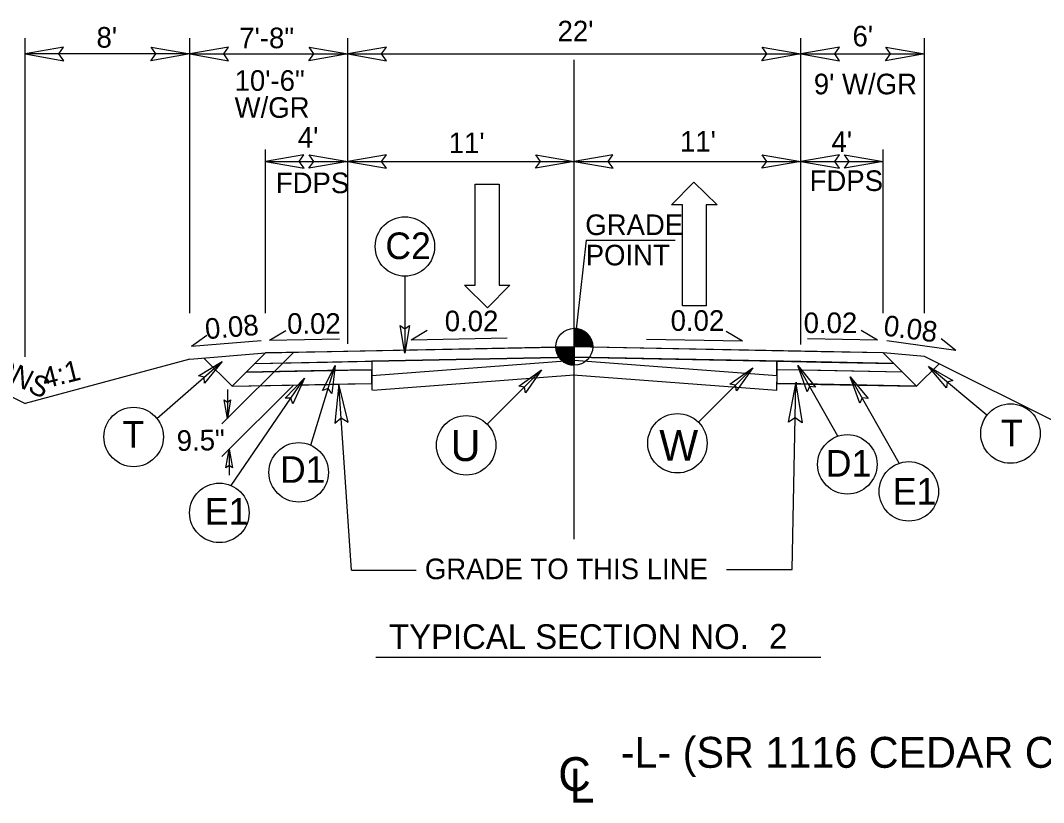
# Model space of a CAD drawing. Extents: x 573732 to 574187, y -53389 to -53257.
# Drawn here: x 573830.28 to 573879.96, y -53323.15 to -53285.19 of the extents above; entities that cross this region are included whole.
import ezdxf

# ---------------------------------------------------------------- set-up
doc = ezdxf.new("R2010")
doc.units = 0
for name, color, linetype in [('Old_Level_11', 7, 'Continuous'), ('Prop Dimension', 7, 'Continuous'), ('Prop Lane Arrow CELL', 7, 'Continuous'), ('Prop Shade Heavy', 7, 'Continuous'), ('Prop Shade Light', 7, 'Continuous'), ('Prop Shade Medium', 7, 'Continuous'), ('Typical Grade Point Symbol CELL', 7, 'Continuous'), ('Typical ID Circle CELL', 7, 'Continuous'), ('Typical Pavement Slope CELL', 7, 'Continuous'), ('Typical Pavement Slope Information CELL', 7, 'Continuous'), ('Typical Shoulder Slope CELL', 7, 'Continuous'), ('Typical Shoulder Slope Information CELL', 7, 'Continuous'), ('Typical Slope Point Local CELL', 7, 'Continuous'), ('Typical Terminator CELL', 7, 'Continuous'), ('Typical Text Centerline CELL', 7, 'Continuous'), ('Typical Text General CELL', 7, 'Continuous'), ('Typical Text Grade Point CELL', 7, 'Continuous'), ('Typical Text ID Circle CELL', 7, 'Continuous'), ('Typical Text Label CELL', 7, 'Continuous')]:
    doc.layers.add(name, color=color, linetype=linetype)

msp = doc.modelspace()

# ---------------------------------------------------------------- linework, layer by layer
at = {"layer": 'Old_Level_11'}
for points in [[(573840.48, -53303.606), (573840.325, -53304.506), (573840.165, -53303.601), (573840.325, -53303.716)], [(573840.255, -53306.905), (573840.41, -53306.005), (573840.57, -53306.91), (573840.41, -53306.795)]]:
    msp.add_lwpolyline(points, close=True, dxfattribs=at)
at = {"layer": 'Prop Dimension'}
for p, q in [((573830.501, -53301.516), (573830.501, -53286.055)), ((573838.501, -53299.402), (573838.501, -53286.055)), ((573846.171, -53300.89), (573846.171, -53286.055)), ((573868.171, -53300.915), (573868.171, -53286.055)), ((573874.171, -53299.402), (573874.171, -53286.055)), ((573838.501, -53286.812), (573830.501, -53286.812)), ((573838.501, -53286.812), (573846.171, -53286.812)), ((573846.171, -53286.812), (573868.171, -53286.812)), ((573868.171, -53286.812), (573874.171, -53286.812)), ((573842.171, -53299.402), (573842.171, -53291.451)), ((573872.171, -53299.402), (573872.171, -53291.451)), ((573842.171, -53292.027), (573846.171, -53292.027)), ((573846.171, -53292.027), (573857.171, -53292.027)), ((573857.171, -53292.027), (573868.171, -53292.027)), ((573868.171, -53292.027), (573872.171, -53292.027)), ((573857.747, -53295.851), (573857.171, -53301.028)), ((573857.747, -53295.851), (573862.067, -53295.851)), ((573843.529, -53301.301), (573840.059, -53304.772)), ((573843.529, -53302.885), (573840.059, -53306.356)), ((573840.325, -53303.109), (573840.325, -53304.506)), ((573846.356, -53311.868), (573845.741, -53302.84)), ((573867.742, -53311.834), (573867.936, -53302.827)), ((573840.41, -53306.005), (573840.41, -53307.259)), ((573846.356, -53311.868), (573849.496, -53311.868)), ((573864.558, -53311.834), (573867.742, -53311.834))]:
    msp.add_line(p, q, dxfattribs=at)
at = {"layer": 'Prop Lane Arrow CELL'}
for p, q in [((573852.364, -53298.034), (573852.364, -53293.134)), ((573852.364, -53293.134), (573853.519, -53293.134)), ((573853.519, -53293.134), (573853.519, -53298.034)), ((573861.898, -53294.14), (573862.983, -53293.037)), ((573862.983, -53293.037), (573864.103, -53294.14)), ((573862.423, -53294.14), (573861.898, -53294.14)), ((573862.423, -53299.04), (573862.423, -53294.14)), ((573864.103, -53294.14), (573863.578, -53294.14)), ((573863.578, -53294.14), (573863.578, -53299.04)), ((573852.959, -53299.137), (573851.839, -53298.034)), ((573851.839, -53298.034), (573852.364, -53298.034)), ((573854.044, -53298.034), (573852.959, -53299.137)), ((573853.519, -53298.034), (573854.044, -53298.034)), ((573863.578, -53299.04), (573862.423, -53299.04))]:
    msp.add_line(p, q, dxfattribs=at)
at = {"layer": 'Prop Shade Heavy'}
for points in [[(573857.171, -53301.528), (573857.161, -53301.528), (573847.332, -53301.725), (573847.332, -53302.141), (573847.332, -53302.424), (573857.171, -53301.681), (573857.171, -53301.528)], [(573857.181, -53301.528), (573857.171, -53301.528), (573857.171, -53301.681), (573867.009, -53302.424), (573867.009, -53302.141), (573867.009, -53301.725), (573857.181, -53301.528)]]:
    msp.add_lwpolyline(points, dxfattribs=at)
at = {"layer": 'Prop Shade Light'}
for p, q in [((573857.171, -53301.028), (573845.175, -53301.268)), ((573869.166, -53301.268), (573857.171, -53301.028)), ((573842.171, -53301.329), (573841.66, -53301.84)), ((573845.175, -53301.268), (573842.171, -53301.329)), ((573847.332, -53301.725), (573857.161, -53301.528)), ((573857.161, -53301.528), (573857.171, -53301.528)), ((573872.171, -53301.329), (573869.166, -53301.268)), ((573872.681, -53301.84), (573872.171, -53301.329)), ((573841.66, -53301.84), (573845.185, -53301.767)), ((573845.185, -53301.767), (573847.332, -53301.725)), ((573867.009, -53301.725), (573869.156, -53301.767)), ((573869.156, -53301.767), (573872.681, -53301.84))]:
    msp.add_line(p, q, dxfattribs=at)
msp.add_lwpolyline([(573857.171, -53301.528), (573857.181, -53301.528), (573867.009, -53301.725)], dxfattribs=at)
at = {"layer": 'Prop Shade Medium'}
for p, q in [((573841.234, -53302.265), (573840.554, -53302.946)), ((573845.193, -53302.184), (573841.234, -53302.265)), ((573847.332, -53302.141), (573845.193, -53302.184)), ((573847.332, -53302.424), (573847.332, -53302.141)), ((573847.332, -53302.725), (573847.332, -53302.424)), ((573869.148, -53302.184), (573867.009, -53302.141)), ((573873.107, -53302.265), (573869.148, -53302.184)), ((573873.787, -53302.946), (573873.107, -53302.265)), ((573840.554, -53302.946), (573845.207, -53302.851)), ((573847.332, -53302.808), (573847.332, -53302.725)), ((573867.009, -53302.725), (573867.009, -53302.808)), ((573867.009, -53302.808), (573867.922, -53302.826)), ((573867.951, -53302.827), (573869.135, -53302.851)), ((573869.135, -53302.851), (573873.787, -53302.946))]:
    msp.add_line(p, q, dxfattribs=at)
for points in [[(573867.009, -53302.141), (573867.009, -53302.424), (573867.009, -53302.725)], [(573845.207, -53302.851), (573845.741, -53302.84), (573847.332, -53302.808)], [(573867.922, -53302.826), (573867.938, -53302.743), (573867.951, -53302.827)]]:
    msp.add_lwpolyline(points, dxfattribs=at)
at = {"layer": 'Typical Grade Point Symbol CELL'}
for p, q in [((573857.171, -53301.028), (573857.171, -53300.132)), ((573856.275, -53301.028), (573857.171, -53301.028)), ((573857.169, -53301.923), (573857.171, -53301.028)), ((573857.171, -53301.028), (573857.169, -53301.923)), ((573858.066, -53301.028), (573857.171, -53301.028))]:
    msp.add_line(p, q, dxfattribs=at)
for points in [[(573857.179, -53300.132), (573857.179, -53300.132), (573857.179, -53301.028)], [(573857.196, -53300.132), (573857.196, -53301.028)], [(573857.214, -53300.134), (573857.214, -53301.028)], [(573857.232, -53300.134), (573857.232, -53301.028)], [(573857.25, -53300.136), (573857.25, -53301.028)], [(573857.268, -53300.138), (573857.268, -53301.028)], [(573857.286, -53300.14), (573857.286, -53301.028)], [(573857.304, -53300.142), (573857.304, -53301.028)], [(573857.322, -53300.144), (573857.322, -53301.028)], [(573857.34, -53300.148), (573857.34, -53301.028)], [(573857.358, -53300.152), (573857.358, -53301.028)], [(573857.376, -53300.156), (573857.376, -53301.028)], [(573857.393, -53300.16), (573857.393, -53301.028)], [(573857.411, -53300.166), (573857.411, -53301.028)], [(573857.429, -53300.17), (573857.429, -53301.028)], [(573857.447, -53300.176), (573857.447, -53301.028)], [(573857.465, -53300.182), (573857.465, -53301.028)], [(573857.483, -53300.188), (573857.483, -53301.028)], [(573857.501, -53300.196), (573857.501, -53301.028)], [(573857.519, -53300.204), (573857.519, -53301.028)], [(573857.537, -53300.212), (573857.537, -53301.028)], [(573857.555, -53300.22), (573857.555, -53301.028)], [(573857.572, -53300.228), (573857.572, -53301.028)], [(573857.59, -53300.238), (573857.59, -53301.028)], [(573857.608, -53300.248), (573857.608, -53301.028)], [(573857.626, -53300.258), (573857.626, -53301.028)], [(573857.644, -53300.268), (573857.644, -53301.028)], [(573857.662, -53300.28), (573857.662, -53301.028)], [(573857.68, -53300.292), (573857.68, -53301.028)], [(573857.698, -53300.305), (573857.698, -53301.028)], [(573857.716, -53300.317), (573857.716, -53301.028)], [(573857.734, -53300.331), (573857.734, -53301.028)], [(573857.751, -53300.347), (573857.751, -53301.028)], [(573857.769, -53300.363), (573857.769, -53301.028)], [(573857.787, -53300.379), (573857.787, -53301.028)], [(573857.805, -53300.397), (573857.805, -53301.028)], [(573857.823, -53300.415), (573857.823, -53301.028)], [(573857.841, -53300.435), (573857.841, -53301.028)], [(573857.859, -53300.457), (573857.859, -53301.028)], [(573857.877, -53300.479), (573857.877, -53301.028)], [(573857.895, -53300.502), (573857.895, -53301.028)], [(573857.913, -53300.528), (573857.913, -53301.028)], [(573857.931, -53300.556), (573857.931, -53301.028)], [(573857.948, -53300.586), (573857.948, -53301.028)], [(573857.966, -53300.618), (573857.966, -53301.028)], [(573856.279, -53301.028), (573856.279, -53301.125)], [(573856.297, -53301.028), (573856.297, -53301.231)], [(573856.315, -53301.028), (573856.315, -53301.294)], [(573856.333, -53301.028), (573856.333, -53301.348)], [(573856.351, -53301.028), (573856.351, -53301.39)], [(573856.369, -53301.028), (573856.369, -53301.427)], [(573856.387, -53301.028), (573856.387, -53301.461)], [(573856.405, -53301.028), (573856.405, -53301.493)], [(573856.423, -53301.028), (573856.423, -53301.521)], [(573856.441, -53301.028), (573856.441, -53301.547)], [(573856.458, -53301.028), (573856.458, -53301.571)], [(573856.476, -53301.028), (573856.476, -53301.593)], [(573856.494, -53301.028), (573856.494, -53301.614)], [(573856.512, -53301.028), (573856.512, -53301.634)], [(573856.53, -53301.028), (573856.53, -53301.654)], [(573856.548, -53301.028), (573856.548, -53301.672)], [(573856.566, -53301.028), (573856.566, -53301.688)], [(573856.584, -53301.028), (573856.584, -53301.704)], [(573856.602, -53301.028), (573856.602, -53301.72)], [(573856.62, -53301.028), (573856.62, -53301.734)], [(573856.637, -53301.028), (573856.637, -53301.748)], [(573856.655, -53301.028), (573856.655, -53301.76)], [(573856.673, -53301.028), (573856.673, -53301.772)], [(573856.691, -53301.028), (573856.691, -53301.784)], [(573856.709, -53301.028), (573856.709, -53301.795)], [(573856.727, -53301.028), (573856.727, -53301.805)], [(573856.745, -53301.028), (573856.745, -53301.815)], [(573856.763, -53301.028), (573856.763, -53301.825)], [(573856.781, -53301.028), (573856.781, -53301.833)], [(573856.799, -53301.028), (573856.799, -53301.841)], [(573856.817, -53301.028), (573856.817, -53301.849)], [(573856.834, -53301.028), (573856.834, -53301.857)], [(573856.852, -53301.028), (573856.852, -53301.865)], [(573856.87, -53301.028), (573856.87, -53301.871)], [(573856.888, -53301.028), (573856.888, -53301.877)], [(573856.906, -53301.028), (573856.906, -53301.883)], [(573856.924, -53301.028), (573856.924, -53301.887)], [(573856.942, -53301.028), (573856.942, -53301.893)], [(573856.96, -53301.028), (573856.96, -53301.897)], [(573856.978, -53301.028), (573856.978, -53301.901)], [(573856.996, -53301.028), (573856.996, -53301.905)], [(573857.013, -53301.028), (573857.013, -53301.909)], [(573857.031, -53301.028), (573857.031, -53301.911)], [(573857.049, -53301.028), (573857.049, -53301.915)], [(573857.067, -53301.028), (573857.067, -53301.917)], [(573857.085, -53301.028), (573857.085, -53301.919)], [(573857.103, -53301.028), (573857.103, -53301.921)], [(573857.121, -53301.028), (573857.121, -53301.921)], [(573857.139, -53301.028), (573857.139, -53301.923)], [(573857.157, -53301.028), (573857.157, -53301.923), (573857.157, -53301.923)], [(573857.984, -53300.656), (573857.984, -53301.028)], [(573858.002, -53300.697), (573858.002, -53301.028)], [(573858.02, -53300.747), (573858.02, -53301.028)], [(573858.038, -53300.809), (573858.038, -53301.028)], [(573858.056, -53300.9), (573858.056, -53301.028)]]:
    msp.add_lwpolyline(points, dxfattribs=at)
msp.add_circle((573857.17, -53301.027), 0.895, dxfattribs=at)
for start, end in [(359.9905, 89.9905), (179.9905, 269.9905)]:
    msp.add_arc((573857.17, -53301.027), 0.895, start, end, dxfattribs=at)
at = {"layer": 'Typical ID Circle CELL'}
for p, q in [((573848.946, -53297.602), (573848.946, -53301.33)), ((573836.907, -53304.513), (573840.075, -53301.735)), ((573844.382, -53305.808), (573845.561, -53301.935)), ((573863.197, -53304.691), (573865.835, -53302.055)), ((573869.966, -53305.369), (573868.02, -53301.939)), ((573877.21, -53304.353), (573874.369, -53301.987)), ((573840.509, -53307.766), (573844.07, -53302.549)), ((573852.941, -53304.789), (573855.579, -53302.153)), ((573872.95, -53306.681), (573870.569, -53302.483))]:
    msp.add_line(p, q, dxfattribs=at)
for centre in [(573848.946, -53296.16), (573835.773, -53305.404), (573878.349, -53305.24), (573851.922, -53305.809), (573862.178, -53305.711), (573870.43, -53306.735), (573843.789, -53307.123), (573873.415, -53308.047), (573839.936, -53309.091)]:
    msp.add_circle(centre, 1.443, dxfattribs=at)
at = {"layer": 'Typical Pavement Slope CELL'}
for p, q in [((573846.171, -53301.248), (573857.171, -53301.028)), ((573868.171, -53301.248), (573857.171, -53301.028)), ((573846.171, -53301.748), (573857.181, -53301.528)), ((573868.171, -53301.748), (573857.161, -53301.528)), ((573846.171, -53302.165), (573847.332, -53302.141)), ((573868.171, -53302.165), (573867.009, -53302.141)), ((573846.171, -53302.831), (573847.345, -53302.808)), ((573868.171, -53302.831), (573866.996, -53302.808))]:
    msp.add_line(p, q, dxfattribs=at)
at = {"layer": 'Typical Pavement Slope Information CELL'}
for p, q in [((573838.579, -53300.991), (573839.332, -53300.471)), ((573842.377, -53300.712), (573843.16, -53300.239)), ((573849.25, -53300.688), (573850.033, -53300.215)), ((573849.25, -53300.688), (573853.91, -53300.595)), ((573865.336, -53300.763), (573864.553, -53300.29)), ((573871.889, -53300.713), (573871.106, -53300.239)), ((573838.579, -53300.991), (573841.964, -53300.716)), ((573842.377, -53300.712), (573845.772, -53300.644)), ((573865.336, -53300.763), (573860.675, -53300.67)), ((573871.889, -53300.713), (573868.494, -53300.645)), ((573875.701, -53301.207), (573872.339, -53300.731)), ((573875.701, -53301.207), (573874.981, -53300.643))]:
    msp.add_line(p, q, dxfattribs=at)
at = {"layer": 'Typical Shoulder Slope CELL'}
for p, q in [((573838.501, -53301.635), (573842.171, -53301.329)), ((573840.554, -53302.946), (573839.185, -53301.578)), ((573840.554, -53302.946), (573842.171, -53301.329)), ((573842.171, -53301.329), (573846.171, -53301.247)), ((573872.171, -53301.329), (573868.171, -53301.247)), ((573874.171, -53301.496), (573872.171, -53301.329)), ((573873.787, -53302.946), (573872.171, -53301.329)), ((573841.66, -53301.84), (573846.171, -53301.747)), ((573847.332, -53302.424), (573857.171, -53301.681)), ((573847.332, -53301.725), (573847.332, -53302.725)), ((573857.171, -53301.681), (573867.009, -53302.424)), ((573867.009, -53301.725), (573867.009, -53302.725)), ((573872.681, -53301.84), (573868.171, -53301.747)), ((573873.787, -53302.946), (573874.882, -53301.851)), ((573841.234, -53302.265), (573846.171, -53302.164)), ((573847.385, -53303.132), (573857.171, -53302.393)), ((573857.117, -53302.389), (573867.009, -53303.136)), ((573873.107, -53302.265), (573868.171, -53302.164)), ((573840.554, -53302.946), (573846.171, -53302.831)), ((573847.332, -53302.724), (573847.332, -53303.136)), ((573867.009, -53303.136), (573867.009, -53302.725)), ((573873.787, -53302.946), (573868.171, -53302.831))]:
    msp.add_line(p, q, dxfattribs=at)
at = {"layer": 'Typical Slope Point Local CELL'}
for p, q in [((573816.884, -53296.978), (573830.501, -53303.786)), ((573896.67, -53312.746), (573874.171, -53301.496)), ((573838.501, -53301.635), (573830.501, -53303.786))]:
    msp.add_line(p, q, dxfattribs=at)
at = {"layer": 'Typical Terminator CELL'}
for points in [[(573832.375, -53286.489), (573830.501, -53286.812), (573832.386, -53287.145), (573832.146, -53286.812)], [(573836.626, -53286.489), (573838.501, -53286.812), (573836.615, -53287.145), (573836.855, -53286.812)], [(573840.375, -53286.489), (573838.501, -53286.812), (573840.386, -53287.145), (573840.146, -53286.812)], [(573844.296, -53286.489), (573846.171, -53286.812), (573844.285, -53287.145), (573844.525, -53286.812)], [(573848.045, -53286.489), (573846.171, -53286.812), (573848.056, -53287.145), (573847.816, -53286.812)], [(573866.296, -53286.489), (573868.171, -53286.812), (573866.285, -53287.145), (573866.525, -53286.812)], [(573870.045, -53286.489), (573868.171, -53286.812), (573870.056, -53287.145), (573869.816, -53286.812)], [(573872.296, -53286.489), (573874.171, -53286.812), (573872.285, -53287.145), (573872.525, -53286.812)], [(573844.045, -53291.705), (573842.171, -53292.027), (573844.056, -53292.361), (573843.816, -53292.027)], [(573844.296, -53291.705), (573846.171, -53292.027), (573844.285, -53292.361), (573844.525, -53292.027)], [(573848.045, -53291.705), (573846.171, -53292.027), (573848.056, -53292.361), (573847.816, -53292.027)], [(573855.296, -53291.705), (573857.171, -53292.027), (573855.285, -53292.361), (573855.525, -53292.027)], [(573859.045, -53291.705), (573857.171, -53292.027), (573859.056, -53292.361), (573858.816, -53292.027)], [(573866.296, -53291.705), (573868.171, -53292.027), (573866.285, -53292.361), (573866.525, -53292.027)], [(573870.045, -53291.705), (573868.171, -53292.027), (573870.056, -53292.361), (573869.816, -53292.027)], [(573870.296, -53291.705), (573872.171, -53292.027), (573870.285, -53292.361), (573870.525, -53292.027)], [(573849.176, -53299.995), (573848.946, -53301.33), (573848.709, -53299.987), (573848.946, -53300.158)], [(573838.919, -53302.442), (573840.075, -53301.735), (573839.222, -53302.799), (573839.194, -53302.508)], [(573844.952, -53303.146), (573845.561, -53301.935), (573845.397, -53303.289), (573845.22, -53303.057)], [(573864.727, -53302.836), (573865.835, -53302.055), (573865.052, -53303.172), (573865.005, -53302.884)], [(573868.479, -53303.214), (573868.02, -53301.939), (573868.889, -53302.99), (573868.599, -53302.959)], [(573875.248, -53303.019), (573874.369, -53301.987), (573875.553, -53302.664), (573875.27, -53302.738)], [(573843.127, -53303.522), (573844.07, -53302.549), (573843.509, -53303.792), (573843.409, -53303.517)], [(573854.471, -53302.935), (573855.579, -53302.153), (573854.797, -53303.27), (573854.75, -53302.982)], [(573871.028, -53303.759), (573870.569, -53302.483), (573871.438, -53303.534), (573871.148, -53303.503)], [(573846.19, -53304.688), (573845.741, -53302.84), (573845.536, -53304.743), (573845.853, -53304.481)], [(573867.573, -53304.694), (573867.936, -53302.827), (573868.229, -53304.719), (573867.901, -53304.472)]]:
    msp.add_lwpolyline(points, close=True, dxfattribs=at)
at = {"layer": 'Typical Text Centerline CELL'}
msp.add_line((573857.171, -53310.372), (573857.171, -53287.093), dxfattribs=at)
at = {"layer": 'Typical Text Label CELL'}
msp.add_line((573847.537, -53316.092), (573869.141, -53316.092), dxfattribs=at)

# ---------------------------------------------------------------- texts
at = {"layer": 'Typical Pavement Slope Information CELL'}
for s, p in [("22'", (573856.359, -53286.203)), ("8'", (573833.971, -53286.508)), ('7\'-8"', (573840.903, -53286.536)), ("6'", (573870.68, -53286.447)), ("9' W/GR", (573868.802, -53288.773)), ("4'", (573843.747, -53291.362)), ("11'", (573851.074, -53291.628)), ("11'", (573862.304, -53291.559)), ("4'", (573869.661, -53291.568)), ('FDPS', (573842.677, -53293.571)), ('FDPS', (573868.596, -53293.466)), ('0.02', (573850.88, -53300.275)), ('0.02', (573861.849, -53300.254))]:
    msp.add_text(s, height=1, rotation=360, dxfattribs=at).set_placement(p)
for s, p in [('10\'-6"', (573840.676, -53288.603)), ('W/GR', (573840.676, -53289.914))]:
    msp.add_text(s, height=1, dxfattribs=at).set_placement(p)
at = {"layer": 'Typical Shoulder Slope Information CELL'}
for s, rotation, p in [('0.08', 4.7615, (573839.283, -53300.664)), ('0.02', 360, (573843.225, -53300.398)), ('0.02', 360, (573868.308, -53300.365)), ('0.08', 352.4054, (573872.148, -53300.473)), ('9.5"', 1.1457, (573837.876, -53306.086))]:
    msp.add_text(s, height=1, rotation=rotation, dxfattribs=at).set_placement(p)
at = {"layer": 'Typical Slope Point Local CELL'}
for s, rotation, p in [('VAR SEE X-SECTIONS', 333.435, (573818.555, -53297.154)), ('4:1', 14.0362, (573831.466, -53303.062))]:
    msp.add_text(s, height=1, rotation=rotation, dxfattribs=at).set_placement(p)
at = {"layer": 'Typical Text Centerline CELL'}
for s, height, rotation, p in [('-L- (SR 1116 CEDAR CREEK RD)', 1.5, 360, (573859.427, -53321.463)), ('L', 1.641, 359.9469, (573856.936, -53323.148))]:
    msp.add_text(s, height=height, rotation=rotation, dxfattribs=at).set_placement(p)
msp.add_text('C', height=1.64, dxfattribs=at).set_placement((573856.39, -53322.588))
at = {"layer": 'Typical Text General CELL'}
msp.add_text('GRADE TO THIS LINE', height=1, dxfattribs=at).set_placement((573849.914, -53312.308))
at = {"layer": 'Typical Text Grade Point CELL'}
for s, p in [('GRADE', (573857.703, -53295.604)), ('POINT', (573857.724, -53297.076))]:
    msp.add_text(s, height=1, dxfattribs=at).set_placement(p)
at = {"layer": 'Typical Text ID Circle CELL'}
for s, height, p in [('C2', 1.2912, (573847.998, -53296.77)), ('T ', 1.2912, (573877.888, -53305.86)), ('T ', 1.2912, (573835.229, -53305.924)), ('U', 1.5, (573851.167, -53306.574)), ('W', 1.5, (573861.295, -53306.562)), ('D1', 1.2912, (573869.384, -53307.329)), ('D1', 1.2912, (573842.882, -53307.63)), ('E1', 1.2912, (573872.634, -53308.691)), ('E1', 1.2912, (573839.226, -53309.659))]:
    msp.add_text(s, height=height, dxfattribs=at).set_placement(p)
at = {"layer": 'Typical Text Label CELL'}
msp.add_text('TYPICAL SECTION NO.  ', height=1.19356, rotation=360, dxfattribs=at).set_placement((573848.177, -53315.692))
msp.add_text('2 ', height=1.1936, dxfattribs=at).set_placement((573866.63, -53315.676))

doc.saveas('drawing.dxf')
